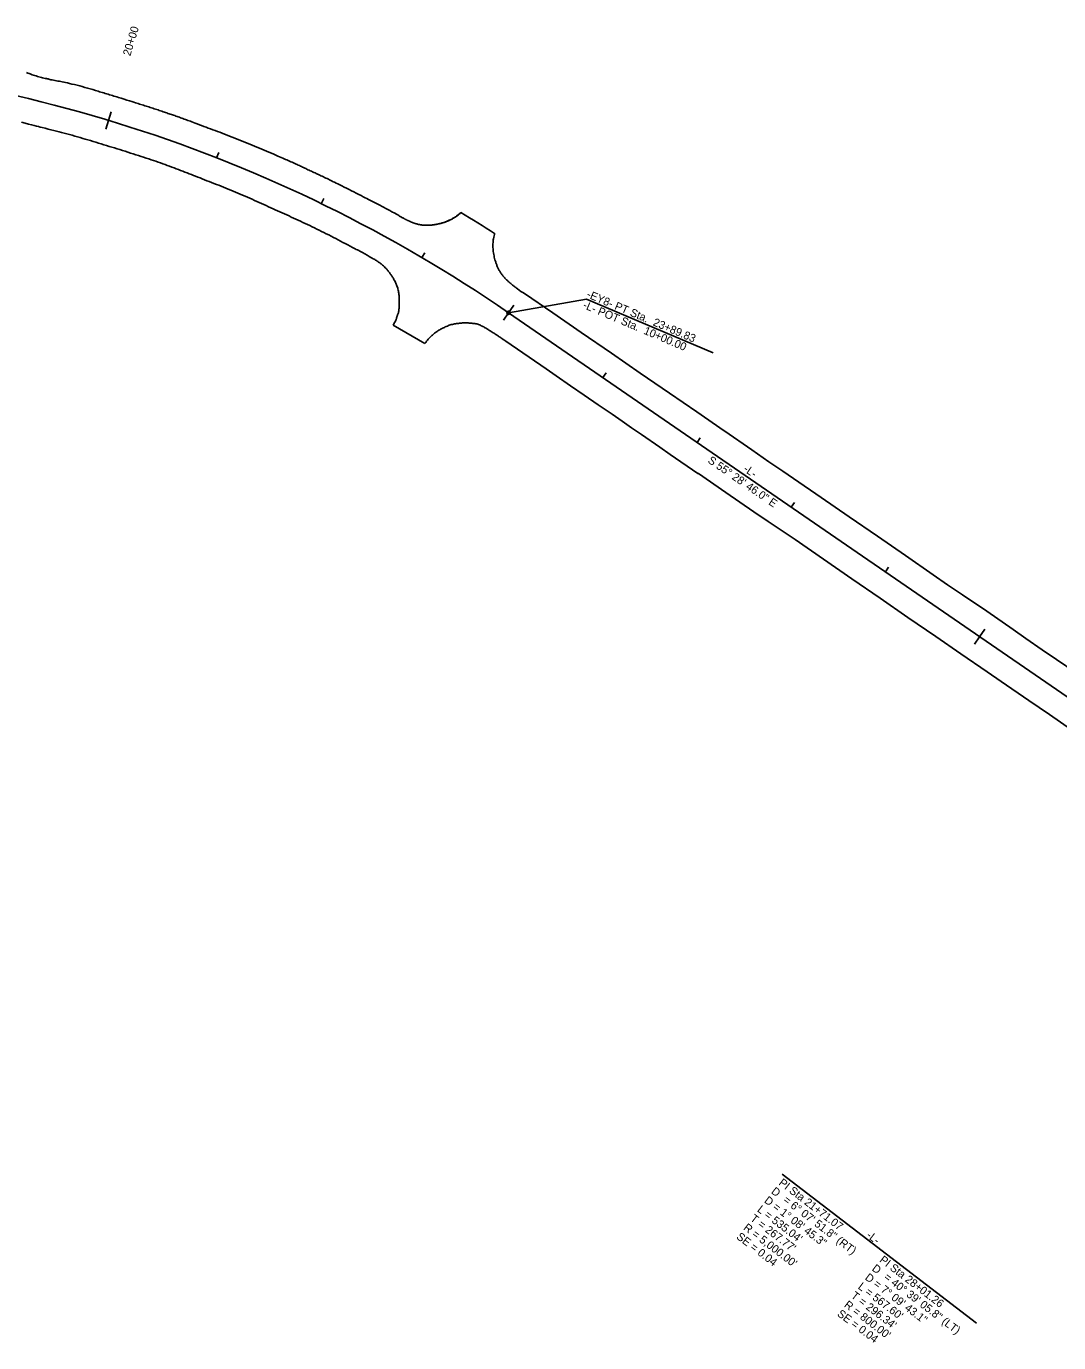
# Model space of a CAD drawing. Extents: x 1616561 to 1622460, y 896726 to 899651.
# Drawn here: x 1617638 to 1618541, y 898215 to 899366 of the extents above; entities that cross this region are included whole.
import ezdxf

# ---------------------------------------------------------------- set-up
doc = ezdxf.new("R2010")
doc.units = 0
for name, color, linetype in [('Prop DSN Text', 7, 'Continuous'), ('Prop EOT', 7, 'Continuous'), ('Prop Horizontal Alignment Tick Label', 7, 'Continuous'), ('Prop Shade Light', 7, 'Continuous'), ('Prop Superelevation  Arrow CELL', 7, 'Continuous'), ('Prop Superelevation Label', 7, 'Continuous'), ('Prop Terminator CELL', 7, 'Continuous'), ('Scratch_Level_1', 7, 'Continuous'), ('Sheet Cutting Line CELL', 7, 'Continuous'), ('Sheet North Arrow CELL', 7, 'Continuous'), ('Sheet Sticker Incomplete CELL', 7, 'Continuous'), ('Sheet Title CELL', 7, 'Continuous')]:
    doc.layers.add(name, color=color, linetype=linetype)

msp = doc.modelspace()

# ---------------------------------------------------------------- linework, layer by layer
at = {"layer": 'Prop DSN Text'}
msp.add_circle((1618059.8, 899115.8), 1.5, dxfattribs=at)
at = {"layer": 'Prop Horizontal Alignment Tick Label'}
for q in [(1617707.5, 899276.4), (1617712.2, 899291.7)]:
    msp.add_line((1617709.9, 899284), q, dxfattribs=at)
at = {"layer": 'Prop Shade Light'}
for p, q in [((1617804.3, 899251.3), (1617806.2, 899256)), ((1617895.9, 899211.2), (1617898.1, 899215.7)), ((1617989.4, 899192.3), (1617989.4, 899192.3)), ((1617984, 899164), (1617986.6, 899168.3)), ((1618059.8, 899115.8), (1618801.3, 898605.7)), ((1618801.3, 898605.7), (1618059.8, 899115.8)), ((1617958.9, 899104.8), (1617986.6, 899089))]:
    msp.add_line(p, q, dxfattribs=at)
for points in [[(1617989.4, 899192.3), (1617989.4, 899192.3)], [(1618556.2, 898800.7), (1618539, 898812.5), (1618526.6, 898820.9), (1618512.2, 898830.8), (1618501, 898838.7), (1618478.1, 898854.6), (1618456.7, 898869), (1618443.7, 898877.9), (1618431.3, 898886.6), (1618406.9, 898903.4), (1618382.5, 898920.3), (1618357.8, 898937.2), (1618333.3, 898954.1), (1618309, 898970.9), (1618299.7, 898977.1), (1618287.5, 898985.5), (1618272.5, 898995.9), (1618248.8, 899012.3), (1618248.3, 899012.5), (1618224.3, 899029.1), (1618200.5, 899045.5), (1618174.9, 899063), (1618149.7, 899080.3), (1618123.2, 899098.6), (1618098.4, 899115.7), (1618073.6, 899132.5)], [(1618057.4, 899090.8), (1618092.8, 899066.7), (1618101.4, 899060.7), (1618113.8, 899052), (1618126, 899043.6), (1618138.2, 899035.3), (1618150.5, 899027), (1618159.2, 899021), (1618167.3, 899015.2), (1618175.9, 899009.4), (1618192.1, 898998.2), (1618201.1, 898991.9), (1618225.4, 898975.3), (1618226, 898975.1), (1618249.9, 898958.6), (1618274.4, 898941.7), (1618286.9, 898933.2), (1618310.4, 898917.3), (1618335.1, 898900.2), (1618360, 898883.1), (1618384.7, 898866.1), (1618409, 898849.3), (1618433.4, 898832.6), (1618455.4, 898817.5), (1618478.3, 898801.7), (1618490.6, 898793.2), (1618514.9, 898776.5), (1618532.8, 898764.2), (1618555.1, 898748.8)]]:
    msp.add_lwpolyline(points, dxfattribs=at)
for radius, start, end in [(1263.5, 55.4794, 89.0571), (1263.5, 55.4794, 89.0571), (1314.7, 57.635, 59.1446)]:
    msp.add_arc((1617343.8, 898074.8), radius, start, end, dxfattribs=at)
for points, degree in [([(1617960.3, 899202.8), (1617956.5, 899204.8), (1617952.7, 899206.9), (1617948.9, 899208.9), (1617944.3, 899211.4), (1617939.6, 899213.8), (1617935, 899216.1), (1617926.6, 899220.4), (1617918.1, 899224.7), (1617909.7, 899228.9), (1617905.4, 899231), (1617901.1, 899233.1), (1617896.7, 899235.2), (1617892.6, 899237.1), (1617888.4, 899239.1), (1617884.2, 899241), (1617880.5, 899242.7), (1617876.8, 899244.6), (1617873, 899246.3), (1617868.3, 899248.5), (1617863.4, 899250.5), (1617858.6, 899252.6), (1617850.2, 899256.2), (1617841.8, 899259.8), (1617833.4, 899263.3), (1617824.6, 899266.9), (1617815.8, 899270.4), (1617807, 899273.7), (1617799.1, 899276.6), (1617791.3, 899279.6), (1617783.5, 899282.5), (1617779.2, 899284.1), (1617775, 899285.6), (1617770.7, 899287.2), (1617766.8, 899288.6), (1617762.8, 899289.9), (1617758.8, 899291.2), (1617754.3, 899292.8), (1617749.7, 899294.3), (1617745.1, 899295.8), (1617740.5, 899297.3), (1617735.8, 899298.7), (1617731.2, 899300.2), (1617721, 899303.4), (1617710.8, 899306.5), (1617700.6, 899309.6), (1617691.5, 899312.4), (1617682.4, 899314.8), (1617673.2, 899317), (1617668.2, 899318.1), (1617663.1, 899318.9), (1617658.1, 899320), (1617655.7, 899320.6), (1617653.4, 899321.1), (1617651.1, 899321.7), (1617648.8, 899322.3), (1617646.5, 899322.9), (1617644.2, 899323.6), (1617642.1, 899324.3), (1617640.1, 899325.2), (1617638, 899325.9)], 3), ([(1617633.7, 899282.4), (1617643.1, 899280.1), (1617652.5, 899277.7), (1617661.9, 899275.3), (1617671.2, 899272.9), (1617680.4, 899270.4), (1617689.5, 899267.7), (1617698.9, 899265), (1617708.2, 899262.1), (1617717.5, 899259.2), (1617726.8, 899256.3), (1617736, 899253.3), (1617745.2, 899250.3), (1617753.3, 899247.6), (1617761.3, 899244.7), (1617769.2, 899241.7), (1617776.7, 899238.8), (1617784.2, 899235.9), (1617791.7, 899233), (1617800, 899229.7), (1617808.4, 899226.5), (1617816.7, 899223.1), (1617825.1, 899219.7), (1617833.4, 899216), (1617841.8, 899212.2), (1617849.8, 899208.6), (1617857.7, 899205), (1617865.7, 899201.4), (1617873.8, 899197.7), (1617881.9, 899193.9), (1617889.9, 899190.1), (1617898.3, 899186), (1617906.6, 899181.7), (1617914.8, 899177.4), (1617923.4, 899173), (1617931.9, 899168.4), (1617940.3, 899163.7), (1617942.9, 899162.3), (1617945.4, 899160.6), (1617947.8, 899158.9), (1617949.6, 899157.5), (1617951.1, 899156), (1617952.7, 899154.4), (1617953.7, 899153.4), (1617954.6, 899152.3), (1617955.4, 899151.2), (1617957.2, 899148.8), (1617958.7, 899146.3), (1617960.1, 899143.7), (1617960.9, 899142.3), (1617961.5, 899140.9), (1617962.1, 899139.4), (1617962.8, 899137.5), (1617963.3, 899135.7), (1617963.6, 899133.8), (1617963.9, 899131.9), (1617964, 899130), (1617964.1, 899128.1), (1617964.2, 899126.8), (1617964.2, 899125.4), (1617964.2, 899124.1), (1617964.2, 899122.3), (1617964.2, 899120.5), (1617963.9, 899118.8), (1617963.7, 899117.3), (1617963.4, 899115.8), (1617962.9, 899114.4), (1617962.6, 899113.6), (1617962.3, 899112.7), (1617962, 899111.9), (1617961.7, 899111), (1617961.6, 899110.1), (1617961.1, 899109.3), (1617960.4, 899107.8), (1617959.6, 899106.3), (1617958.9, 899104.8)], 3), ([(1617989.4, 899192.3), (1617988.8, 899192.3), (1617988.2, 899192.3), (1617987.6, 899192.3), (1617986.8, 899192.3), (1617985.9, 899192.3), (1617985.1, 899192.4), (1617984.7, 899192.5), (1617984.2, 899192.5), (1617983.8, 899192.6), (1617983.4, 899192.7), (1617982.9, 899192.7), (1617982.5, 899192.8), (1617981.7, 899193), (1617980.8, 899193.1), (1617980, 899193.3), (1617979.1, 899193.6), (1617978.3, 899193.8), (1617977.4, 899194.1), (1617976.6, 899194.4), (1617975.8, 899194.7), (1617975, 899195), (1617974.3, 899195.3), (1617973.6, 899195.6), (1617972.9, 899196), (1617972.2, 899196.3), (1617971.5, 899196.6), (1617970.8, 899196.9), (1617970.1, 899197.3), (1617969.4, 899197.6), (1617968.7, 899198), (1617968.1, 899198.3), (1617967.4, 899198.7), (1617966.7, 899199.1), (1617964.6, 899200.3), (1617962.4, 899201.6), (1617960.3, 899202.8)], 3), ([(1618018.1, 899203.4), (1618017, 899202.4), (1618015.8, 899201.5), (1618014.6, 899200.6), (1618013.9, 899200.1), (1618013.2, 899199.6), (1618012.5, 899199.1), (1618011.8, 899198.6), (1618011, 899198.2), (1618010.2, 899197.8), (1618008.7, 899197), (1618007.1, 899196.2), (1618005.4, 899195.6), (1618005, 899195.4), (1618004.6, 899195.3), (1618004.2, 899195.1), (1618003.8, 899195), (1618003.4, 899194.9), (1618002.9, 899194.7), (1618002.1, 899194.4), (1618001.3, 899194.2), (1618000.4, 899194), (1617999.6, 899193.8), (1617998.7, 899193.6), (1617997.9, 899193.4), (1617997, 899193.2), (1617996.1, 899193), (1617995.3, 899192.9), (1617994.9, 899192.8), (1617994.4, 899192.7), (1617994, 899192.7), (1617993.6, 899192.6), (1617993.2, 899192.6), (1617992.7, 899192.5), (1617991.9, 899192.4), (1617991, 899192.3), (1617990.2, 899192.3), (1617990.2, 899192.3), (1617990.2, 899192.3), (1617990.2, 899192.3)], 3), ([(1617990.2, 899192.3), (1617989.9, 899192.3), (1617989.7, 899192.3), (1617989.4, 899192.3)], 2), ([(1617986.6, 899089), (1617987.2, 899089.7), (1617987.7, 899090.4), (1617988.3, 899091.2), (1617989.3, 899092.6), (1617990.5, 899093.8), (1617991.8, 899095), (1617992.4, 899095.6), (1617993.1, 899096.1), (1617993.8, 899096.7), (1617994.5, 899097.3), (1617995.1, 899097.9), (1617995.8, 899098.4), (1617998.7, 899100.6), (1618002, 899102.2), (1618005.4, 899103.8), (1618007.1, 899104.5), (1618008.8, 899105.2), (1618010.6, 899105.6), (1618012.4, 899106), (1618014.2, 899106.3), (1618016.1, 899106.5), (1618017.7, 899106.7), (1618019.4, 899106.9), (1618021, 899107), (1618022.7, 899107), (1618024.3, 899106.9), (1618026, 899106.7), (1618029.4, 899106.4), (1618032.8, 899106), (1618036, 899104.4), (1618038.8, 899103), (1618041.3, 899101.4), (1618043.9, 899099.8), (1618045.5, 899098.8), (1618047.1, 899097.9), (1618048.6, 899096.9), (1618050.1, 899095.9), (1618051.6, 899094.8), (1618053.1, 899093.8), (1618054.5, 899092.8), (1618056, 899091.8), (1618057.4, 899090.8)], 3)]:
    msp.add_open_spline(points, degree=degree, dxfattribs=at)
msp.add_spline([(1618073.6, 899132.5), (1618067.7, 899136.6), (1618065.5, 899138.3), (1618063.3, 899140), (1618061.1, 899141.8), (1618059, 899143.7), (1618057, 899145.6), (1618055.2, 899147.6), (1618053.5, 899149.9), (1618052.7, 899151), (1618052, 899152.2), (1618050.7, 899154.6), (1618049.6, 899157), (1618048.7, 899159.5), (1618047.9, 899162.1), (1618047.3, 899164.5), (1618046.8, 899166.9), (1618046.4, 899169.3), (1618046.2, 899171.7), (1618046.1, 899176.2), (1618046.6, 899180.6), (1618047.6, 899185.3)], degree=3, dxfattribs=at)
at = {"layer": 'Prop Superelevation  Arrow CELL'}
for p, q in [((1618142.2, 899059.1), (1618145, 899063.2)), ((1618224.6, 899002.4), (1618227.4, 899006.5)), ((1618307, 898945.8), (1618309.8, 898949.9)), ((1618389.4, 898889.1), (1618392.2, 898893.2))]:
    msp.add_line(p, q, dxfattribs=at)
at = {"layer": 'Prop Superelevation Label'}
for p, q in [((1618059.8, 899115.8), (1618064.3, 899122.4)), ((1618059.8, 899115.8), (1618055.3, 899109.2)), ((1618471.8, 898832.4), (1618476.3, 898839)), ((1618471.8, 898832.4), (1618467.2, 898825.8))]:
    msp.add_line(p, q, dxfattribs=at)
at = {"layer": 'Prop Terminator CELL'}
msp.add_line((1617986.6, 899089), (1617958.9, 899104.8), dxfattribs=at)
for points in [[(1618073.6, 899132.5), (1618098.4, 899115.7), (1618123.2, 899098.6), (1618149.7, 899080.3), (1618174.9, 899063), (1618200.5, 899045.5), (1618224.3, 899029.1), (1618248.3, 899012.5), (1618248.8, 899012.3), (1618272.5, 898995.9), (1618287.5, 898985.5), (1618299.7, 898977.1), (1618309, 898970.9), (1618333.3, 898954.1), (1618357.8, 898937.2), (1618382.5, 898920.3), (1618406.9, 898903.4), (1618431.3, 898886.6), (1618443.7, 898877.9), (1618456.7, 898869), (1618478.1, 898854.6), (1618501, 898838.7), (1618512.2, 898830.8), (1618526.6, 898820.9), (1618539, 898812.5), (1618556.2, 898800.7)], [(1618555.1, 898748.8), (1618532.8, 898764.2), (1618514.9, 898776.5), (1618490.6, 898793.2), (1618478.3, 898801.7), (1618455.4, 898817.5), (1618433.4, 898832.6), (1618409, 898849.3), (1618384.7, 898866.1), (1618360, 898883.1), (1618335.1, 898900.2), (1618310.4, 898917.3), (1618286.9, 898933.2), (1618274.4, 898941.7), (1618249.9, 898958.6), (1618226, 898975.1), (1618225.4, 898975.3), (1618201.1, 898991.9), (1618192.1, 898998.2), (1618175.9, 899009.4), (1618167.3, 899015.2), (1618159.2, 899021), (1618150.5, 899027), (1618138.2, 899035.3), (1618126, 899043.6), (1618113.8, 899052), (1618101.4, 899060.7), (1618092.8, 899066.7), (1618057.4, 899090.8)]]:
    msp.add_lwpolyline(points, dxfattribs=at)
msp.add_arc((1617343.8, 898074.8), 1314.7, 57.635, 59.1446, dxfattribs=at)
for points in [[(1617638, 899325.9), (1617640.1, 899325.2), (1617642.1, 899324.3), (1617644.2, 899323.6), (1617646.5, 899322.9), (1617648.8, 899322.3), (1617651.1, 899321.7), (1617653.4, 899321.1), (1617655.7, 899320.6), (1617658.1, 899320), (1617663.1, 899318.9), (1617668.2, 899318.1), (1617673.2, 899317), (1617682.4, 899314.8), (1617691.5, 899312.4), (1617700.6, 899309.6), (1617710.8, 899306.5), (1617721, 899303.4), (1617731.2, 899300.2), (1617735.8, 899298.7), (1617740.5, 899297.3), (1617745.1, 899295.8), (1617749.7, 899294.3), (1617754.3, 899292.8), (1617758.8, 899291.2), (1617762.8, 899289.9), (1617766.8, 899288.6), (1617770.7, 899287.2), (1617775, 899285.6), (1617779.2, 899284.1), (1617783.5, 899282.5), (1617791.3, 899279.6), (1617799.1, 899276.6), (1617807, 899273.7), (1617815.8, 899270.4), (1617824.6, 899266.9), (1617833.4, 899263.3), (1617841.8, 899259.8), (1617850.2, 899256.2), (1617858.6, 899252.6), (1617863.4, 899250.5), (1617868.3, 899248.5), (1617873, 899246.3), (1617876.8, 899244.6), (1617880.5, 899242.7), (1617884.2, 899241), (1617888.4, 899239.1), (1617892.6, 899237.1), (1617896.7, 899235.2), (1617901.1, 899233.1), (1617905.4, 899231), (1617909.7, 899228.9), (1617918.1, 899224.7), (1617926.6, 899220.4), (1617935, 899216.1), (1617939.6, 899213.8), (1617944.3, 899211.4), (1617948.9, 899208.9), (1617952.7, 899206.9), (1617956.5, 899204.8), (1617960.3, 899202.8)], [(1617958.9, 899104.8), (1617959.6, 899106.3), (1617960.4, 899107.8), (1617961.1, 899109.3), (1617961.6, 899110.1), (1617961.7, 899111), (1617962, 899111.9), (1617962.3, 899112.7), (1617962.6, 899113.6), (1617962.9, 899114.4), (1617963.4, 899115.8), (1617963.7, 899117.3), (1617963.9, 899118.8), (1617964.2, 899120.5), (1617964.2, 899122.3), (1617964.2, 899124.1), (1617964.2, 899125.4), (1617964.2, 899126.8), (1617964.1, 899128.1), (1617964, 899130), (1617963.9, 899131.9), (1617963.6, 899133.8), (1617963.3, 899135.7), (1617962.8, 899137.5), (1617962.1, 899139.4), (1617961.5, 899140.9), (1617960.9, 899142.3), (1617960.1, 899143.7), (1617958.7, 899146.3), (1617957.2, 899148.8), (1617955.4, 899151.2), (1617954.6, 899152.3), (1617953.7, 899153.4), (1617952.7, 899154.4), (1617951.1, 899156), (1617949.6, 899157.5), (1617947.8, 899158.9), (1617945.4, 899160.6), (1617942.9, 899162.3), (1617940.3, 899163.7), (1617931.9, 899168.4), (1617923.4, 899173), (1617914.8, 899177.4), (1617906.6, 899181.7), (1617898.3, 899186), (1617889.9, 899190.1), (1617881.9, 899193.9), (1617873.8, 899197.7), (1617865.7, 899201.4), (1617857.7, 899205), (1617849.8, 899208.6), (1617841.8, 899212.2), (1617833.4, 899216), (1617825.1, 899219.7), (1617816.7, 899223.1), (1617808.4, 899226.5), (1617800, 899229.7), (1617791.7, 899233), (1617784.2, 899235.9), (1617776.7, 899238.8), (1617769.2, 899241.7), (1617761.3, 899244.7), (1617753.3, 899247.6), (1617745.2, 899250.3), (1617736, 899253.3), (1617726.8, 899256.3), (1617717.5, 899259.2), (1617708.2, 899262.1), (1617698.9, 899265), (1617689.5, 899267.7), (1617680.4, 899270.4), (1617671.2, 899272.9), (1617661.9, 899275.3), (1617652.5, 899277.7), (1617643.1, 899280.1), (1617633.7, 899282.4)], [(1617960.3, 899202.8), (1617962.4, 899201.6), (1617964.6, 899200.3), (1617966.7, 899199.1), (1617967.4, 899198.7), (1617968.1, 899198.3), (1617968.7, 899198), (1617969.4, 899197.6), (1617970.1, 899197.3), (1617970.8, 899196.9), (1617971.5, 899196.6), (1617972.2, 899196.3), (1617972.9, 899196), (1617973.6, 899195.6), (1617974.3, 899195.3), (1617975, 899195), (1617975.8, 899194.7), (1617976.6, 899194.4), (1617977.4, 899194.1), (1617978.3, 899193.8), (1617979.1, 899193.6), (1617980, 899193.3), (1617980.8, 899193.1), (1617981.7, 899193), (1617982.5, 899192.8), (1617982.9, 899192.7), (1617983.4, 899192.7), (1617983.8, 899192.6), (1617984.2, 899192.5), (1617984.7, 899192.5), (1617985.1, 899192.4), (1617985.9, 899192.3), (1617986.8, 899192.3), (1617987.6, 899192.3), (1617988.5, 899192.3), (1617989.3, 899192.3), (1617990.2, 899192.3), (1617990.3, 899192.3), (1617990.4, 899192.3), (1617990.5, 899192.3)], [(1618057.4, 899090.8), (1618056, 899091.8), (1618054.5, 899092.8), (1618053.1, 899093.8), (1618051.6, 899094.8), (1618050.1, 899095.9), (1618048.6, 899096.9), (1618047.1, 899097.9), (1618045.5, 899098.8), (1618043.9, 899099.8), (1618041.3, 899101.4), (1618038.8, 899103), (1618036, 899104.4), (1618032.8, 899106), (1618029.4, 899106.4), (1618026, 899106.7), (1618024.3, 899106.9), (1618022.7, 899107), (1618021, 899107), (1618019.4, 899106.9), (1618017.7, 899106.7), (1618016.1, 899106.5), (1618014.2, 899106.3), (1618012.4, 899106), (1618010.6, 899105.6), (1618008.8, 899105.2), (1618007.1, 899104.5), (1618005.4, 899103.8), (1618002, 899102.2), (1617998.7, 899100.6), (1617995.8, 899098.4), (1617995.1, 899097.9), (1617994.5, 899097.3), (1617993.8, 899096.7), (1617993.1, 899096.1), (1617992.4, 899095.6), (1617991.8, 899095), (1617990.5, 899093.8), (1617989.3, 899092.6), (1617988.3, 899091.2), (1617987.7, 899090.4), (1617987.2, 899089.7), (1617986.6, 899089)]]:
    msp.add_open_spline(points, degree=3, dxfattribs=at)
for points in [[(1617989.4, 899192.3), (1617990.2, 899192.3), (1617992.7, 899192.5), (1617994, 899192.7), (1617995.3, 899192.9), (1617997.9, 899193.4), (1618000.4, 899194), (1618002.9, 899194.7), (1618004.2, 899195.1), (1618005.4, 899195.6), (1618010.2, 899197.8), (1618012.5, 899199.1), (1618014.6, 899200.6), (1618018.1, 899203.4)], [(1618047.6, 899185.3), (1618046.6, 899180.6), (1618046.1, 899176.2), (1618046.2, 899171.7), (1618046.4, 899169.3), (1618046.8, 899166.9), (1618047.3, 899164.5), (1618047.9, 899162.1), (1618048.7, 899159.5), (1618049.6, 899157), (1618050.7, 899154.6), (1618052, 899152.2), (1618052.7, 899151), (1618053.5, 899149.9), (1618055.2, 899147.6), (1618057, 899145.6), (1618059, 899143.7), (1618061.1, 899141.8), (1618063.3, 899140), (1618065.5, 899138.3), (1618067.7, 899136.6), (1618073.6, 899132.5)]]:
    msp.add_spline(points, degree=3, dxfattribs=at)
at = {"layer": 'Sheet Cutting Line CELL'}
msp.add_line((1618059.8, 899115.8), (1618804, 898603.9), dxfattribs=at)
at = {"layer": 'Sheet North Arrow CELL'}
for p, q in [((1618059.8, 899115.8), (1618127.8, 899127.6)), ((1618127.8, 899127.6), (1618238.6, 899080.7))]:
    msp.add_line(p, q, dxfattribs=at)
msp.add_circle((1618059.8, 899115.8), 1.5, dxfattribs=at)
at = {"layer": 'Sheet Sticker Incomplete CELL'}
msp.add_line((1618299.1, 898362.1), (1618469.2, 898231.8), dxfattribs=at)
at = {"layer": 'Sheet Title CELL'}
msp.add_arc((1617343.8, 898074.8), 1263.5, 55.4794, 89.0571, dxfattribs=at)
msp.add_arc((1617343.8, 898074.8), 1263.5, 55.4794, 89.0571, dxfattribs=at)

# ---------------------------------------------------------------- texts
at = {"layer": 'Prop EOT'}
msp.add_text('20+00', height=7, rotation=73.1578, dxfattribs=at).set_placement((1617728.9, 899340))
at = {"layer": 'Scratch_Level_1'}
for s, p in [('S 55%%d 28\' 46.0" E', (1618233.4, 898985.2)), ('-L-', (1618264.6, 898977.7))]:
    msp.add_text(s, height=7, rotation=325.4794, dxfattribs=at).set_placement(p)
at = {"layer": 'Sheet North Arrow CELL'}
for s, p in [('-EY8- PT Sta.  23+89.83 ', (1618127.5, 899129.5)), ('-L- POT Sta.  10+00.00', (1618124.2, 899120.1))]:
    msp.add_text(s, height=7, rotation=337.0441, dxfattribs=at).set_placement(p)
at = {"layer": 'Sheet Sticker Incomplete CELL'}
for s, rotation, p in [('D', 322.554, (1618288.9, 898346)), ('PI Sta 21+71.07', 322.554, (1618295.5, 898353.5)), ('D = 1%%d 08\' 45.3"', 322.554, (1618282.8, 898338)), ('= 6%%d 07\' 51.8" (RT)', 322.554, (1618299.3, 898338.4)), ("T = 267.77'", 322.554, (1618270.6, 898322.2)), ("L = 535.04'", 322.554, (1618276.7, 898330.1)), ("R = 5,000.00'", 322.554, (1618264.6, 898314.2)), ('SE = 0.04', 322.554, (1618258.5, 898306.3)), ('-L-', 322.554, (1618372.2, 898307.5)), ('D', 322.554, (1618377, 898278.5)), ('PI Sta 28+01.26', 322.554, (1618383.6, 898286)), ('D = 7%%d 09\' 43.1"', 322.554, (1618370.9, 898270.6)), ('= 40%%d 39\' 05.8" (LT)', 322.554, (1618387.4, 898270.9)), ("T = 296.34'", 322.554, (1618358.7, 898254.7)), ("L = 567.60'", 322.554, (1618364.8, 898262.6)), ("R = 800.00'", 322.554, (1618352.7, 898246.7)), ('SE = 0.04', 323.3262, (1618346.6, 898238.8))]:
    msp.add_text(s, height=7, rotation=rotation, dxfattribs=at).set_placement(p)

doc.saveas('drawing.dxf')
